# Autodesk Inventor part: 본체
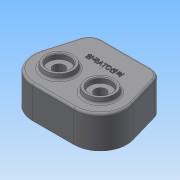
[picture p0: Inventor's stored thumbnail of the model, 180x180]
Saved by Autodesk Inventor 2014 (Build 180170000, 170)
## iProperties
Created: 2014-12
Part Number: 본체
Material: 일반
Document SubType Name: Modeling
Designer: user
Density: 1 g/cm^3
Appearance: 기본값
Author: user
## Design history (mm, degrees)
sketch "스케치1"
  geometry: L1 (-47, 36)-(47, 36); L2 (47, 36)-(62.752, -18.127); L3 (28.186, -64.186)-(-28.186, -64.186); L4 (-62.752, -18.127)-(-47, 36); L5 (-28.186, -28.186)-(0, 0); L6 (0, 0)-(28.186, -28.186); C1 r 46 at (0, 0); A1 r 36 centre (28.186, -28.186) between (28.186, -64.186) and (62.752, -18.127); A2 r 36 centre (-28.186, -28.186) between (-62.752, -18.127) and (-28.186, -64.186); 3 further points
  constraints: 12 end point, 4 point on circle, 4 tangent, 3 centre point, 2 midpoint, 2 vertical alignment, 1 coincident, 1 equal length, 1 equal radius, 1 horizontal, 1 parallel
  dimensions: "d6" = 94 distance of L1.start L1.end; "d7" = 36 radius of A2; "d10" = 36 distance from line of L1 point (0, 0); "d11" = 92 diameter of C1; "d42" = 90 deg angle of L6 L5
extrude "돌출1" new body sketch "스케치1" distance "d12" = 44; taper "d13" = 0 deg
fillet "모깎기1" dims "d14" = 18
sketch "스케치2"
  geometry: C1 r 20 at (-28.186, -28.186); C2 r 20 at (28.186, -28.186); 3 further points
  constraints: 2 centre point, 2 coincident, 1 equal radius
  dimensions: "d15" = 40 diameter of C1
extrude "돌출2" join sketch "스케치2" distance "d16" = 7; taper "d17" = -10 deg
sketch "스케치3"
  geometry: C1 r 18.766 at (0, 0) reference; C2 r 18.766 at (56.372, 0) reference; 3 further points
  constraints: 2 coincident
hole "구멍1" sketch "스케치3" at (0, 0), (56.372, 0) diameter "d18" = 30; stored, may be unused: countersink angle "d22" = 90 deg, drill point angle "d24" = 0 deg; dims "d19" = 6, "d20" = 4, "d21" = 2, "d23" = 7
sketch "스케치4"
  geometry: L1 (-50.775, 23.03)-(-62.752, -18.127) reference; L2 (-28.186, -64.186)-(28.186, -64.186) reference; L3 (62.752, -18.127)-(50.775, 23.03) reference; L4 (33.492, 36)-(-33.492, 36) reference; L5 (33.492, 31)-(-33.492, 31); L6 (-45.974, 21.633)-(-47.997, 14.681); L7 (-52.468, -0.681)-(-57.951, -19.524); L8 (57.951, -19.524)-(52.468, -0.681); L9 (47.997, 14.681)-(45.974, 21.633); L10 (-28.186, -59.186)-(-8, -59.186); L11 (8, -59.186)-(28.186, -59.186); A1 r 18 centre (-33.492, 18) between (-33.492, 36) and (-50.775, 23.03) reference; A2 r 36 centre (-28.186, -28.186) between (-62.752, -18.127) and (-28.186, -64.186) reference; A3 r 36 centre (28.186, -28.186) between (28.186, -64.186) and (62.752, -18.127) reference; A4 r 18 centre (33.492, 18) between (50.775, 23.03) and (33.492, 36) reference; A5 r 13 centre (-33.492, 18) between (-33.492, 31) and (-45.974, 21.633); A6 r 31 centre (-28.186, -28.186) between (-57.951, -19.524) and (-28.186, -59.186); A7 r 31 centre (28.186, -28.186) between (28.186, -59.186) and (57.951, -19.524); A8 r 13 centre (33.492, 18) between (45.974, 21.633) and (33.492, 31); A9 r 8 centre (-50.232, 7) between (-52.468, -0.681) and (-47.997, 14.681); A10 r 8 centre (50.232, 7) between (47.997, 14.681) and (52.468, -0.681); A11 r 8 centre (0, -59.186) between (8, -59.186) and (-8, -59.186); 1 further point
  constraints: 14 end point, 14 point on circle, 7 centre point, 2 equal radius, 1 horizontal alignment, 1 vertical alignment, 1 other
  dimensions: "d25" = 5 distance between parallel lines of L5 L4; "d27" = 8 radius of A9; "d28" = 5 radial gap between concentric circles of A1 A5; "d29" = 5 distance between parallel lines of L1 L6; "d30" = 5 distance between parallel lines of L1 L7; "d31" = 5 radial gap between concentric circles of A2 A6; "d32" = 5 distance between parallel lines of L2 L10; "d33" = 5 distance between parallel lines of L2 L11; "d34" = 5 radial gap between concentric circles of A3 A7; "d35" = 5 distance between parallel lines of L3 L8; "d36" = 5 distance from line of L3 A10.centre; "d37" = 5 distance between parallel lines of L3 L9; "d38" = 5 distance from line of L1 A9.centre; "d39" = 5 distance from line of L2 A11.centre; "d81" = 29 distance from line of A10.centre L4
extrude "돌출3" cut sketch "스케치4" distance "d40" = 34; taper "d41" = 0 deg
sketch "스케치5"
  geometry: L1 (-47.997, 14.681)-(-45.974, 21.633) reference; L2 (-57.951, -19.524)-(-52.468, -0.681) reference; L3 (-8, -59.186)-(-28.186, -59.186) reference; L4 (28.186, -59.186)-(8, -59.186) reference; L5 (52.468, -0.681)-(57.951, -19.524) reference; L6 (45.974, 21.633)-(47.997, 14.681) reference; L7 (-33.492, 31)-(33.492, 31) reference; C1 r 17.5 at (-28.186, -28.186); C2 r 17.5 at (28.186, -28.186); C3 r 20 at (0, 0); A1 r 13 centre (-33.492, 18) between (-33.492, 31) and (-45.974, 21.633) reference; A2 r 8 centre (-50.232, 7) between (-52.468, -0.681) and (-47.997, 14.681) reference; A3 r 31 centre (-28.186, -28.186) between (-57.951, -19.524) and (-28.186, -59.186) reference; A4 r 8 centre (0, -59.186) between (8, -59.186) and (-8, -59.186) reference; A5 r 31 centre (28.186, -28.186) between (28.186, -59.186) and (57.951, -19.524) reference; A6 r 8 centre (50.232, 7) between (47.997, 14.681) and (52.468, -0.681) reference; A7 r 13 centre (33.492, 18) between (45.974, 21.633) and (33.492, 31) reference; A8 r 24 centre (-28.186, -28.186) between (-23.547, -4.639) and (-4.639, -23.547); A9 r 24 centre (28.186, -28.186) between (4.639, -23.547) and (23.547, -4.639); A10 r 24 centre (0, 0) between (-4.639, -23.547) and (4.639, -23.547); A11 r 24 centre (0, 0) between (23.547, -4.639) and (-23.547, -4.639); 1 further point
  constraints: 8 point on circle, 7 centre point, 6 coincident, 4 equal radius
  dimensions: "d43" = 48 diameter of A8; "d44" = 35 diameter of C1; "d45" = 40 diameter of C3
extrude "돌출4" join sketch "스케치5" distance "d46" = 11; taper "d47" = 0 deg
sketch "스케치6"
  geometry: C1 r 10 at (0, 0); 1 further point
  constraints: 1 centre point, 1 coincident
  dimensions: "d48" = 20 diameter of C1
extrude "돌출5" cut sketch "스케치6" distance "d49" = 3; taper "d50" = 0 deg
sketch "스케치7"
  geometry: C1 r 15 at (56.372, 0) reference; C2 r 15 at (0, 0) reference; 3 further points
  constraints: 2 coincident
hole "구멍2" sketch "스케치7" at (0, 0), (56.372, 0) diameter "d51" = 15.5; stored, may be unused: countersink angle "d55" = 90 deg, drill point angle "d57" = 0 deg; dims "d52" = 6, "d53" = 4, "d54" = 2, "d56" = 10
sketch "스케치8"
  geometry: L1 (-47.997, 14.681)-(-45.974, 21.633) reference; L2 (-33.492, 31)-(33.492, 31) reference; L3 (45.974, 21.633)-(47.997, 14.681) reference; L4 (52.468, -0.681)-(57.951, -19.524) reference; L5 (28.186, -59.186)-(8, -59.186) reference; L6 (-8, -59.186)-(-28.186, -59.186) reference; L7 (-57.951, -19.524)-(-52.468, -0.681) reference; L8 (-50.775, 23.03)-(-62.752, -18.127) reference; L9 (-28.186, -64.186)-(28.186, -64.186) reference; L10 (62.752, -18.127)-(50.775, 23.03) reference; L11 (33.492, 36)-(-33.492, 36) reference; A1 r 13 centre (-33.492, 18) between (-33.492, 31) and (-45.974, 21.633) reference; A2 r 13 centre (33.492, 18) between (45.974, 21.633) and (33.492, 31) reference; A3 r 8 centre (50.232, 7) between (47.997, 14.681) and (52.468, -0.681) reference; A4 r 31 centre (28.186, -28.186) between (28.186, -59.186) and (57.951, -19.524) reference; A5 r 8 centre (0, -59.186) between (8, -59.186) and (-8, -59.186) reference; A6 r 31 centre (-28.186, -28.186) between (-57.951, -19.524) and (-28.186, -59.186) reference; A7 r 8 centre (-50.232, 7) between (-52.468, -0.681) and (-47.997, 14.681) reference; A8 r 18 centre (-33.492, 18) between (-33.492, 36) and (-50.775, 23.03) reference; A9 r 36 centre (-28.186, -28.186) between (-62.752, -18.127) and (-28.186, -64.186) reference; A10 r 36 centre (28.186, -28.186) between (28.186, -64.186) and (62.752, -18.127) reference; A11 r 18 centre (33.492, 18) between (50.775, 23.03) and (33.492, 36) reference; 4 further points
  constraints: 3 coincident
hole "구멍3" sketch "스케치8" at (-50.232, 7), (50.232, 7), (0, -59.186) diameter "d58" = 4.134; stored, may be unused: countersink angle "d62" = 90 deg, drill point angle "d64" = 118 deg; dims "d59" = 20, "d60" = 4, "d61" = 2, "d63" = 23
fillet "모깎기2" dims "d65" = 0.1
fillet "모깎기3" dims "d66" = 0.3
fillet "모깎기4" dims "d67" = 3
fillet "모깎기5" dims "d68" = 3
chamfer "모따기1" distance "d69" = 1; stored, may be unused: second distance "d70" = 2, angle "d71" = 45 deg
chamfer "모따기2" distance "d72" = 1; stored, may be unused: second distance "d73" = 2, angle "d74" = 45 deg
chamfer "모따기3" distance "d75" = 1; stored, may be unused: second distance "d76" = 2, angle "d77" = 45 deg
sketch "스케치9"
  geometry: L1 (33.492, 36)-(-33.492, 36) reference; 2 further points
  constraints: 1 vertical alignment, 1 other
  dimensions: "d78" = 30 distance from line of point (0, 6) L1
feature "엠보싱1" sketch "스케치9" dims "d6" = 94, "d7" = 36, "d10" = 36, "d11" = 92, "d42" = 90 deg, "d79" = 1, "d80" = 0
sketch "스케치10"
  geometry: 1 further point
chamfer "모따기4" distance "d82" = 1; stored, may be unused: second distance "d83" = 2, angle "d84" = 45 deg
chamfer "모따기5" distance "d85" = 1; stored, may be unused: second distance "d86" = 2, angle "d87" = 45 deg
fillet "모깎기6" dims "d88" = 3
node "솔리드1"
node "투영된 루프1"
node "투영된 루프2"
node "투영된 루프3"
node "투영된 루프4"
node "투영된 루프5"
node "투영된 루프6"
node "투영된 루프7"
